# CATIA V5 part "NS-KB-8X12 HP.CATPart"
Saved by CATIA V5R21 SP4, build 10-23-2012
Part number: NS-KB-8X12
Source: Unknown
Bounding box of the stored display mesh (mm): x -5.992 to 5.992, y -5.992 to 5.992, z 0 to 12
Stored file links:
  G:\すぐ消す\NS-KB-8X12 HP.CATPart
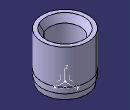
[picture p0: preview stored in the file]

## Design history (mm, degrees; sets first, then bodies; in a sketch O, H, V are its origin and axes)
AxisSystem1: origin (0, 0, 0), X (1, 0, 0), Y (0, 1, 0), Z (0, 0, 1)
Body1 (main body)
  Solid1 "ﾊﾟｰﾂ ﾎﾞﾃﾞｨｰ": solid without history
